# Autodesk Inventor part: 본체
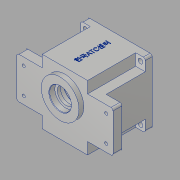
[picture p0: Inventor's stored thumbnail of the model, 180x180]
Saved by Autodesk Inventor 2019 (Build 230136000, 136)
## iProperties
Created: 2020-01
Part Number: 본체
Material: 알루미늄 6061
Document SubType Name: Modeling
Designer: 323-10
Density: 2.7 g/cm^3
Appearance: 알루미늄 - 평지
Mass: 876.342 g
Surface Area: 793.825 cm^2
Volume: 324.571 cm^3
Author: 323-10
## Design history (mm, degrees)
sketch "스케치1"
  geometry: L1 (-47, -47)-(47, -47); L2 (47, -47)-(47, 47); L3 (47, 47)-(-47, 47); L4 (-47, 47)-(-47, -47); L5 (-47, -47)-(47, 47); L6 (47, -47)-(-47, 47); 1 further point
  constraints: 12 end point, 2 midpoint, 2 parallel, 1 horizontal, 1 perpendicular
  dimensions: "d0" = 94 distance of L3.end L2.end; "d1" = 94 distance of L2.end L1.end
extrude "돌출1" new body sketch "스케치1" distance "d2" = 80; taper "d3" = 0 deg
sketch "스케치2"
  geometry: L1 (70, -30)-(-70, -30); L2 (-70, -30)-(-70, 30); L3 (-70, 30)-(70, 30); L4 (70, 30)-(70, -30); L5 (70, -30)-(-70, 30); L6 (-70, -30)-(70, 30); 1 further point
  constraints: 12 end point, 2 midpoint, 2 parallel, 1 horizontal, 1 perpendicular
  dimensions: "d4" = 140 distance of L2.end L3.end; "d5" = 60 distance of L1.end L2.end
extrude "돌출2" join sketch "스케치2" distance "d6" = 13; taper "d7" = 0 deg
sketch "스케치3"
  geometry: C1 r 27.5 at (0, 11); 1 further point
  constraints: 1 centre point, 1 vertical alignment
  dimensions: "d8" = 55 diameter of C1; "d9" = 11 distance of point (0, 0) C1.centre
extrude "돌출3" join sketch "스케치3" distance "d10" = 7; taper "d11" = 0 deg
sketch "스케치4"
  geometry: C1 r 27.5 at (0, 0) reference; C2 r 16 at (0, 0); 1 further point
  constraints: 1 centre point, 1 coincident
  dimensions: "d12" = 32 diameter of C2
extrude "돌출4" cut sketch "스케치4" distance "d13" = 8.3; taper "d14" = 0 deg
sketch "스케치5"
  geometry: C1 r 40 at (0, 0); 1 further point
  constraints: 1 centre point, 1 coincident
  dimensions: "d15" = 80 diameter of C1
extrude "돌출5" cut sketch "스케치5" distance "d16" = 71; taper "d17" = 0 deg
sketch "스케치6"
  geometry: C1 r 21 at (0, 11); C2 r 15 at (0, -20); 1 further point
  constraints: 2 centre point, 2 vertical alignment
  dimensions: "d18" = 11 distance of point (0, 0) C1.centre; "d20" = 20 distance of C2.centre point (0, 0); "d21" = 21 radius of C1; "d22" = 15 radius of C2
extrude "돌출6" join sketch "스케치6" distance "d23" = 7; taper "d24" = 0 deg
sketch "스케치7"
  geometry: C1 r 17.5 at (0, 11); A1 r 21 centre (0, 11) between (8.978, -7.984) and (-8.978, -7.984) reference; 1 further point
  constraints: 1 centre point, 1 coincident
  dimensions: "d25" = 35 diameter of C1
extrude "돌출7" cut sketch "스케치7" distance "d26" = 10; taper "d27" = 0 deg
sketch "스케치8"
  geometry: C1 r 11 at (0, -20); A1 r 15 centre (0, -20) between (-8.978, -7.984) and (8.978, -7.984) reference; 1 further point
  constraints: 1 centre point, 1 coincident
  dimensions: "d28" = 22 diameter of C1
extrude "돌출8" cut sketch "스케치8" distance "d29" = 7; taper "d30" = 0 deg
sketch "스케치9"
  geometry: C1 r 11 at (0, 0) reference; C2 r 9.5 at (0, 0); 1 further point
  constraints: 1 centre point, 1 coincident
  dimensions: "d31" = 19 diameter of C2
extrude "돌출9" cut sketch "스케치9" distance "d32" = 3; taper "d33" = 0 deg
sketch "스케치10"
  geometry: C1 r 16 at (0, 0) reference; C2 r 12.5 at (0, 0); 1 further point
  constraints: 1 centre point, 1 coincident
  dimensions: "d34" = 25 diameter of C2
extrude "돌출10" cut sketch "스케치10" extent not by distance; stored distance "d35" = 3; taper "d36" = 0 deg
sketch "스케치11"
  geometry: C1 r 43 at (0, 0); 1 further point
  constraints: 1 centre point, 1 coincident
  dimensions: "d37" = 86 diameter of C1
extrude "돌출11" cut sketch "스케치11" distance "d38" = 9; taper "d39" = 0 deg
sketch "스케치12" dims "d40" = 36
  geometry: L1 (36, -4)-(39.799, -4); L2 (36, 4)-(39.799, 4); A1 r 4 centre (36, 0) between (36, 4) and (36, -4); A2 r 40 centre (0, 0) between (39.799, -4) and (39.799, 4) reference; A3 r 40 centre (0, 0) between (39.799, -4) and (39.799, 4); A4 r 4 centre (36, 0) between (40, 0) and (36, 4); A5 r 4 centre (36, 0) between (36, -4) and (40, 0); 2 further points
  constraints: 11 point on circle, 4 centre point, 4 end point, 4 tangent, 2 coincident, 2 horizontal, 2 horizontal alignment, 2 other
  dimensions: "d42" = 4 radius of A4
extrude "돌출12" join sketch "스케치12" stored distance "d43" = 9; taper "d44" = 0 deg
fillet "모깎기1" dims "d45" = 3
sketch "스케치13"
  geometry: 2 further points
  dimensions: "d46" = 19 vertical distance of point (0, 0) point (-60, 19); "d47" = 60 horizontal distance of point (0, 0) point (-60, 19)
hole "구멍1" sketch "스케치13" at (-60, 19) diameter "d48" = 4.5; stored, may be unused: countersink angle "d52" = 90 deg, drill point angle "d54" = 118 deg; dims "d49" = 6, "d50" = 10, "d51" = 5, "d53" = 8
sketch "스케치14"
  geometry: L1 (47, 30)-(47, 47) reference; L2 (47, 47)-(33, 47); L3 (33, 47)-(33, 30); L4 (33, 30)-(47, 30); L5 (47, 30)-(47, 47); 1 further point
  constraints: 8 end point, 2 parallel, 1 horizontal, 1 perpendicular
  dimensions: "d55" = 33 distance from line of point (0, 0) L3; "d56" = 30 distance from line of point (0, 0) L4
extrude "돌출13" cut sketch "스케치14" distance "d57" = 70; taper "d58" = 0 deg
sketch "스케치15"
  geometry: C1 r 3.5 at (40, 40); 1 further point
  constraints: 1 centre point
  dimensions: "d59" = 7 diameter of C1; "d60" = 40 horizontal distance of point (0, 0) C1.centre; "d61" = 40 horizontal distance of point (0, 0) C1.centre
extrude "돌출14" cut sketch "스케치15" extent not by distance; stored distance "d62" = 70; taper "d63" = 0 deg
chamfer "모따기1" distance "d64" = 0.8; stored, may be unused: second distance "d65" = 2, angle "d66" = 30 deg
chamfer "모따기2" distance "d67" = 1; stored, may be unused: second distance "d68" = 2, angle "d69" = 45 deg
fillet "모깎기2" dims "d70" = 3
chamfer "모따기3" distance "d71" = 1; stored, may be unused: second distance "d72" = 2, angle "d73" = 45 deg
sketch "스케치16"
  geometry: A1 r 4 centre (36, 0) between (36, 4) and (36, -4) reference; 2 further points
  constraints: 1 coincident
hole "구멍2" sketch "스케치16" at (36, 0) diameter "d74" = 3.242; stored, may be unused: countersink angle "d78" = 90 deg, drill point angle "d80" = 118 deg; dims "d75" = 7, "d76" = 10, "d77" = 5, "d79" = 9
fillet "모깎기3" dims "d81" = 3
sketch "스케치17"
  geometry: L1 (0, 0)-(-66, 0) reference; L2 (-77, 80)-(11, 80) reference; 3 further points
  constraints: 1 midpoint, 1 vertical alignment, 1 other
  dimensions: "d82" = 40 distance from line of L2 point (-33, 40)
feature "엠보싱1" sketch "스케치17" dims "d83" = 0.5, "d84" = 0
node "솔리드1"
mirror "미러1"
mirror "미러2"
mirror "미러3"
mirror "미러4"
mirror "미러5"
mirror "미러6"
mirror "미러7"
mirror "미러8"
node "작업 평면1"
